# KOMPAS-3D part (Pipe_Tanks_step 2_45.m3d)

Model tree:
1. X Axis
2. Y Axis
3. Z Axis  (labels: Pipe Dn 50; T-Bend Dn 50)
     Òîëùèíà ñòåíêè 1 = 1

Referenced files in C:\Documents and Settings\kashirsky\Мои документы\Camtasia Studio\Pipelines3D\Tanks\: Tanks_step 2.a3d
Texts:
  Pipe Dn 50
  Steel ASTM A295
  Three Point Plane
  Plane at Angle
  Line and Point Plane
  Axis through Two Vertices
  Axis of Feature
  Axis of Conical Surface
  Axis through Edge
  Trim by Surface
  Trim by Sketch
  Feature with No History
  Intersection Axis of Two Planes
  Two Line Plane
  Line and Face Plane
  Bend by line
  Hole in sheet body
  Cut in sheet body
  Point in CM
  Linear Dimension from Line to Point
  Surface Finish Symbol
  Geometric Tolerance Symbol
  Leader #1
  Leader #2
  Leader #3
  Shape Deviations and Datum
  Node point number
  Mark of coordination axis
  Node point designation
  Mark/Reference designation with leader
  Mark/reference designation on line
  Mark/Reference designation without leader
  T-Bend Dn 50
  Plane of section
